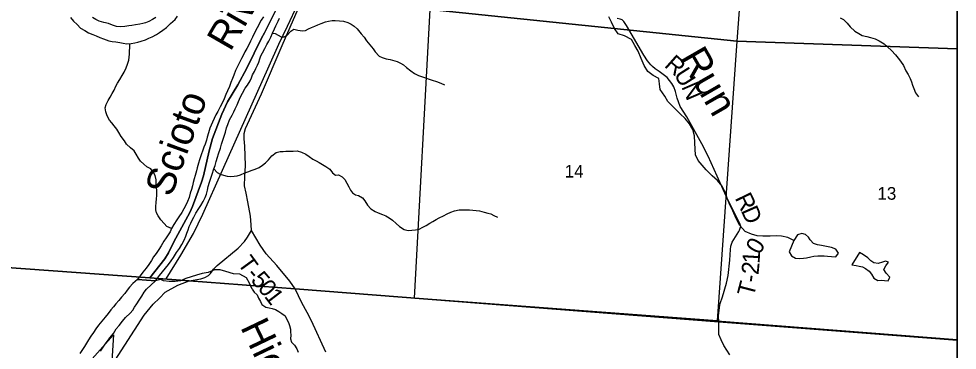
# Model space of a CAD drawing. Extents: x 5.6 to 39.6, y 0.7 to 22.7.
# Drawn here: x 11.957 to 15.052, y 17.991 to 19.086 of the extents above; entities that cross this region are included whole.
import ezdxf

# ---------------------------------------------------------------- set-up
doc = ezdxf.new("R2010")
doc.units = 0
doc.layers.add('Default', color=7, linetype='Continuous')
doc.layers.add('SH_Data', color=7, linetype='Continuous')

msp = doc.modelspace()

# ---------------------------------------------------------------- linework, layer by layer
at = {"layer": 'Default'}
for p, q in [((15.0518, 18.9873), (15.0518, 19.9373)), ((15.0518, 18.027), (15.0518, 18.9873)), ((12.4074, 18.221), (12.3477, 18.2256)), ((12.3477, 18.2256), (12.4074, 18.221))]:
    msp.add_line(p, q, dxfattribs=at)
for points in [[(15.0518, 18.0251), (15.0518, 21.7074), (8.2518, 21.7074), (8.2518, 18.5322)], [(15.0518, 18.0251), (15.0518, 21.7074), (8.2518, 21.7074), (8.2518, 18.5322)], [(15.0518, 18.0251), (15.0518, 21.7074), (10.4881, 21.7074)], [(15.0518, 19.9373), (14.3975, 19.9797), (14.3249, 19.0118), (15.0518, 18.9873)], [(10.5195, 18.3665), (12.3885, 18.2305), (12.4384, 18.2931), (12.4507, 18.3136), (12.4676, 18.3499), (12.5207, 18.446), (12.5299, 18.4665), (12.5594, 18.5468), (12.5656, 18.5673), (12.5844, 18.65), (12.5953, 18.691), (12.6263, 18.7713), (12.6456, 18.8122), (12.6786, 18.8682), (12.7086, 18.9228), (12.7572, 19.0227), (12.7672, 19.0401), (12.8142, 19.1341)], [(12.8142, 19.1341), (12.7672, 19.0401), (12.7572, 19.0227), (12.7086, 18.9228), (12.6786, 18.8682), (12.6456, 18.8122), (12.6263, 18.7713), (12.5953, 18.691), (12.5844, 18.65), (12.5656, 18.5673), (12.5594, 18.5468), (12.5299, 18.4665), (12.5207, 18.446), (12.4676, 18.3499), (12.4507, 18.3136), (12.4384, 18.2931), (12.3885, 18.2305), (12.519, 18.2209), (12.8677, 18.1945), (14.2655, 18.0848), (15.0518, 18.0251)], [(12.4428, 18.2276), (12.4916, 18.306), (12.5333, 18.3772), (12.5635, 18.4407), (12.6282, 18.5865), (12.7827, 18.9308), (12.8148, 19.0023), (12.8424, 19.0618), (12.8771, 19.1341)], [(12.519, 18.2209), (12.5566, 18.2268), (12.5707, 18.2322), (12.582, 18.2382), (12.5885, 18.2451), (12.5949, 18.2531), (12.5987, 18.2588), (12.6112, 18.2713), (12.6805, 18.3283), (12.701, 18.3507), (12.7112, 18.3648), (12.7244, 18.3867), (12.7236, 18.4055), (12.7205, 18.4347), (12.712, 18.4813), (12.7063, 18.5105), (12.7009, 18.5342), (12.7018, 18.565), (12.704, 18.602), (12.7021, 18.6657), (12.7002, 18.6892), (12.6999, 18.7076), (12.7041, 18.7233), (12.7567, 18.8386), (12.8253, 18.9985), (12.8776, 19.1189)], [(12.1272, 19.0901), (12.1377, 19.0786), (12.1492, 19.0671), (12.1604, 19.0555), (12.174, 19.0474), (12.1871, 19.04), (12.2011, 19.0338), (12.2116, 19.0295), (12.2244, 19.0244), (12.2361, 19.0197), (12.2538, 19.0134), (12.2652, 19.0114), (12.2773, 19.0097), (12.2901, 19.0077), (12.3011, 19.0053), (12.3135, 19.0036), (12.3272, 19.0042), (12.339, 19.0067), (12.3492, 19.0093), (12.3606, 19.0118), (12.3743, 19.0169), (12.3858, 19.0217), (12.3968, 19.0265), (12.4113, 19.0343), (12.4213, 19.0407), (12.432, 19.0485), (12.4435, 19.0575), (12.4573, 19.0706), (12.4722, 19.0834), (12.4807, 19.095)], [(12.4087, 19.0906), (12.3976, 19.0835), (12.3858, 19.0775), (12.3751, 19.0731), (12.3656, 19.0706), (12.3554, 19.0684), (12.3417, 19.0663), (12.3295, 19.0645), (12.3193, 19.0631), (12.306, 19.0606), (12.292, 19.0593), (12.2787, 19.0602), (12.2663, 19.0653), (12.2523, 19.0704), (12.2368, 19.074), (12.2214, 19.078), (12.2112, 19.0834), (12.2003, 19.0908)], [(12.4074, 18.221), (12.4211, 18.238), (12.4308, 18.2508), (12.4408, 18.2621), (12.4508, 18.2745), (12.4593, 18.2873), (12.4666, 18.2978), (12.4774, 18.3144), (12.4863, 18.3272), (12.4948, 18.3411), (12.5022, 18.3555), (12.5081, 18.3687), (12.5112, 18.3785), (12.5148, 18.3891), (12.5187, 18.4), (12.5238, 18.4117), (12.5285, 18.4215), (12.5339, 18.4313), (12.5405, 18.4442), (12.5506, 18.4592), (12.5568, 18.4694), (12.5649, 18.4826), (12.5715, 18.4958), (12.5762, 18.5075), (12.5794, 18.5204), (12.5815, 18.5321), (12.5858, 18.5468), (12.5945, 18.5733), (12.6004, 18.5907), (12.6047, 18.6017), (12.608, 18.6153), (12.6116, 18.6289), (12.6151, 18.6406), (12.6218, 18.6591), (12.6254, 18.6716), (12.6297, 18.6856), (12.6356, 18.7019), (12.6384, 18.7121), (12.642, 18.7257), (12.646, 18.7366), (12.6522, 18.7521), (12.6604, 18.7676), (12.6662, 18.7789), (12.6705, 18.7891), (12.6768, 18.8023), (12.6811, 18.8125), (12.6877, 18.828), (12.694, 18.8404), (12.7036, 18.8567), (12.7114, 18.8672), (12.7195, 18.8811), (12.7238, 18.891), (12.7277, 18.9012), (12.7336, 18.9117), (12.7382, 18.9219), (12.7437, 18.9332), (12.748, 18.9434), (12.7519, 18.9536), (12.7555, 18.9635), (12.7605, 18.9733), (12.7679, 18.9876), (12.7749, 19.0016), (12.7815, 19.0125), (12.7878, 19.0257), (12.7936, 19.0385), (12.8003, 19.0525), (12.805, 19.0634), (12.812, 19.0778), (12.817, 19.0887)], [(12.7633, 19.0932), (12.7563, 19.0815), (12.7431, 19.0566), (12.7322, 19.0355), (12.7275, 19.0257), (12.7213, 19.0128), (12.7155, 19.0007), (12.7092, 18.9883), (12.7026, 18.977), (12.6968, 18.9653), (12.6913, 18.9555), (12.6847, 18.9415), (12.6777, 18.9287), (12.6719, 18.9155), (12.6656, 18.9004), (12.6613, 18.8887), (12.6558, 18.8758), (12.6514, 18.8626), (12.6452, 18.8486), (12.6401, 18.8358), (12.6346, 18.8222), (12.6284, 18.8097), (12.621, 18.7958), (12.6128, 18.7803), (12.6062, 18.7686), (12.5957, 18.7448), (12.5914, 18.7346), (12.5871, 18.7248), (12.5823, 18.7093), (12.578, 18.6953), (12.5759, 18.6851), (12.5712, 18.6722), (12.5669, 18.6621), (12.5637, 18.6518), (12.5578, 18.6364)], [(12.7936, 19.0385), (12.8023, 19.0373), (12.8125, 19.0319), (12.8222, 19.0264), (12.8321, 19.0267), (12.8416, 19.0319), (12.8539, 19.045), (12.8639, 19.0521), (12.8775, 19.0485), (12.8922, 19.0461), (12.9028, 19.0478), (12.9124, 19.0527), (12.9219, 19.0571), (12.9333, 19.0623), (12.9433, 19.0667), (12.9535, 19.0708), (12.968, 19.0759), (12.9786, 19.0784), (12.9904, 19.0802), (12.9999, 19.0808), (13.0146, 19.0799), (13.0275, 19.0779), (13.0422, 19.0739), (13.0528, 19.0688), (13.0633, 19.0622), (13.073, 19.053), (13.086, 19.0369), (13.0957, 19.0258), (13.1039, 19.0139), (13.1147, 19.0005), (13.1255, 18.9871), (13.1326, 18.9768), (13.1453, 18.963), (13.1551, 18.9583), (13.1683, 18.954), (13.1815, 18.9515), (13.2041, 18.9456), (13.2154, 18.9401), (13.2259, 18.9339), (13.2357, 18.9255), (13.2495, 18.9139), (13.2623, 18.905), (13.2751, 18.8988), (13.2853, 18.8953), (13.2981, 18.891), (13.3102, 18.887), (13.3204, 18.8835), (13.3343, 18.8788), (13.3483, 18.8733), (13.3607, 18.8682)], [(14.5132, 18.3534), (14.4928, 18.3642), (14.4723, 18.3681), (14.4541, 18.369), (14.4351, 18.3677), (14.4108, 18.3679), (14.3919, 18.3695), (14.3737, 18.375), (14.3525, 18.3835), (14.3345, 18.4034), (14.3232, 18.427), (14.312, 18.4514), (14.3023, 18.4713), (14.2926, 18.4941), (14.2866, 18.5124), (14.2762, 18.5338), (14.2611, 18.5521), (14.2438, 18.5674), (14.2234, 18.5873), (14.1971, 18.6187), (14.1889, 18.637), (14.1875, 18.6552), (14.1869, 18.6765), (14.1855, 18.7001), (14.1796, 18.7206), (14.1683, 18.739), (14.1548, 18.7566), (14.1375, 18.7726), (14.1179, 18.7918), (14.0976, 18.8132), (14.0871, 18.8308), (14.072, 18.8522), (14.0699, 18.8712), (14.0677, 18.8887), (14.0488, 18.8987), (14.0315, 18.9118), (14.0195, 18.9324), (14.0098, 18.9552), (13.9993, 18.9789), (13.9881, 18.998), (13.9776, 19.0178), (13.9542, 19.0294), (13.933, 19.0364), (13.9218, 19.054), (13.912, 19.0746), (13.9023, 19.0929)], [(14.2655, 18.0848), (14.2646, 18.1053), (14.2678, 18.1329), (14.2699, 18.1454), (14.2771, 18.1676), (14.2907, 18.2125), (14.2965, 18.2382), (14.3016, 18.2886), (14.3037, 18.3238), (14.305, 18.3352), (14.3094, 18.3488), (14.3313, 18.3833), (14.334, 18.3882), (14.3364, 18.3946), (14.3384, 18.4006), (14.3344, 18.4098), (14.2894, 18.5004), (14.2301, 18.6323), (14.21, 18.6736), (14.1598, 18.7621), (14.1384, 18.7962), (14.1323, 18.8123), (14.1283, 18.8241), (14.123, 18.8458), (14.1176, 18.8615), (14.1107, 18.8726), (14.0947, 18.8922), (14.0824, 18.9023), (14.069, 18.912), (14.0555, 18.9206), (14.0473, 18.9283), (14.041, 18.9345), (14.0299, 18.9476), (14.0177, 18.9656), (13.9605, 19.0637), (13.9524, 19.0768), (13.9468, 19.0822), (13.94, 19.0853), (13.9299, 19.0874)], [(14.6657, 19.0896), (14.6762, 19.0841), (14.6886, 19.0715), (14.6983, 19.0592), (14.7136, 19.0458), (14.7275, 19.0373), (14.7384, 19.0314), (14.7535, 19.0275), (14.766, 19.0243), (14.7807, 19.0199), (14.7947, 19.0137), (14.8104, 19.0037), (14.8217, 18.994), (14.8348, 18.981), (14.8478, 18.9668), (14.8568, 18.9565), (14.8646, 18.9457), (14.8743, 18.932), (14.8828, 18.9144), (14.8898, 18.9018), (14.8961, 18.8885), (14.9005, 18.8778), (14.9046, 18.8675), (14.9086, 18.8557), (14.9141, 18.8416), (14.9241, 18.8286)], [(15.0518, 18.9873), (14.3249, 19.0118), (14.2605, 18.0881), (15.0518, 18.027)], [(12.4607, 18.3935), (12.4445, 18.4001), (12.4363, 18.4105), (12.4254, 18.4227), (12.4165, 18.4354), (12.4113, 18.4457), (12.4088, 18.4556), (12.4082, 18.4662), (12.4099, 18.4795), (12.4108, 18.4916), (12.4117, 18.503), (12.4115, 18.5193), (12.4105, 18.5295), (12.4096, 18.5447), (12.4094, 18.5542), (12.4065, 18.5687), (12.4013, 18.5786), (12.3924, 18.5905), (12.3789, 18.5971), (12.3691, 18.6056), (12.3583, 18.6163), (12.352, 18.6262), (12.3442, 18.6389), (12.3371, 18.6496), (12.3248, 18.6596), (12.3117, 18.6726), (12.305, 18.6826), (12.2946, 18.6979), (12.2868, 18.7109), (12.2797, 18.722), (12.2716, 18.7323), (12.2641, 18.7423), (12.2563, 18.7519), (12.2485, 18.7652), (12.2434, 18.7793), (12.2417, 18.7926), (12.2445, 18.8032), (12.2515, 18.8168), (12.2585, 18.8277), (12.265, 18.8391), (12.2709, 18.8508), (12.2771, 18.8636), (12.2826, 18.8738), (12.2896, 18.8855), (12.2977, 18.8986), (12.3043, 18.91), (12.3113, 18.9243), (12.3153, 18.936), (12.3192, 18.9493), (12.3209, 18.9595), (12.3214, 18.969), (12.3219, 18.9788), (12.3225, 18.9914), (12.3226, 19.0035)], [(12.5578, 18.6364), (12.5531, 18.6209), (12.5491, 18.6088), (12.5452, 18.5944), (12.5424, 18.5842), (12.538, 18.569), (12.5356, 18.5581), (12.532, 18.5452), (12.53, 18.5342), (12.526, 18.5225), (12.5224, 18.51), (12.5181, 18.4964), (12.513, 18.4832), (12.5071, 18.4704), (12.5009, 18.4587), (12.4943, 18.4466), (12.485, 18.4323), (12.4785, 18.4221), (12.4684, 18.4067), (12.4607, 18.3935), (12.456, 18.3829), (12.4494, 18.3731), (12.4432, 18.363), (12.4355, 18.3513), (12.4262, 18.3366), (12.4185, 18.3246), (12.4099, 18.3106), (12.4015, 18.2997), (12.3941, 18.2884), (12.3856, 18.2752), (12.3767, 18.2628), (12.3659, 18.2489), (12.3477, 18.2256)], [(12.6004, 18.5907), (12.6105, 18.5781), (12.6207, 18.573), (12.632, 18.5695), (12.6444, 18.5667), (12.6566, 18.5658), (12.6668, 18.566), (12.6774, 18.5674), (12.6877, 18.5711), (12.7022, 18.577), (12.7121, 18.5807), (12.7265, 18.5862), (12.7364, 18.5895), (12.7498, 18.5954), (12.7605, 18.6029), (12.7708, 18.6103), (12.7804, 18.6201), (12.7912, 18.634), (12.8057, 18.6444), (12.8183, 18.6477), (12.8282, 18.6484), (12.8376, 18.649), (12.8482, 18.6493), (12.8619, 18.6495), (12.8752, 18.6497), (12.8895, 18.6461), (12.903, 18.6387), (12.9139, 18.6318), (12.9267, 18.6229), (12.9372, 18.6167), (12.9474, 18.6113), (12.9583, 18.6047), (12.9692, 18.5985), (12.9827, 18.5896), (12.9917, 18.5778), (13.0014, 18.5697), (13.0109, 18.5703), (13.0233, 18.5645), (13.0315, 18.5549), (13.0382, 18.5434), (13.0452, 18.5308), (13.0508, 18.5205), (13.0575, 18.511), (13.0672, 18.5052), (13.0771, 18.5024), (13.0898, 18.4946), (13.0977, 18.4847), (13.1073, 18.4705), (13.1178, 18.4583), (13.1317, 18.4494), (13.1415, 18.4451), (13.1566, 18.44), (13.1671, 18.4357), (13.1788, 18.4291), (13.1889, 18.4214), (13.2016, 18.4103), (13.2125, 18.4003), (13.2275, 18.3898), (13.2411, 18.387), (13.2525, 18.3877), (13.2646, 18.389), (13.2768, 18.3919), (13.2898, 18.3975), (13.3004, 18.403), (13.3127, 18.4108), (13.3222, 18.4168), (13.3329, 18.4235), (13.3436, 18.4283), (13.3573, 18.4357), (13.3695, 18.442), (13.3817, 18.448), (13.3939, 18.4524), (13.4087, 18.4549), (13.4193, 18.4551), (13.4318, 18.4553), (13.4428, 18.4552), (13.4545, 18.4543), (13.4651, 18.4534), (13.4761, 18.4518), (13.4912, 18.4478), (13.5037, 18.4443), (13.5138, 18.4415), (13.5236, 18.4368), (13.5353, 18.431)], [(8.2518, 18.5322), (8.2518, 14.9074), (15.0518, 14.9074), (15.0518, 18.0251)], [(15.0518, 18.0251), (14.2655, 18.0848), (12.8677, 18.1945), (12.519, 18.2209), (12.3885, 18.2305), (10.5195, 18.3665), (9.8937, 18.4248), (8.2518, 18.5322)], [(8.2518, 18.5322), (8.2518, 14.9074), (15.0518, 14.9074), (15.0518, 18.0251)], [(15.0518, 18.0251), (14.2655, 18.0848), (12.8677, 18.1945), (12.519, 18.2209), (12.3885, 18.2305), (10.5195, 18.3665), (9.8937, 18.4248), (8.2518, 18.5322)], [(8.2518, 18.5322), (9.8937, 18.4248), (10.5195, 18.3665), (12.3885, 18.2305), (12.519, 18.2209), (12.8677, 18.1945), (14.2655, 18.0848), (15.0518, 18.0251)], [(8.2518, 18.5322), (9.8937, 18.4248), (10.5195, 18.3665), (12.3885, 18.2305), (12.519, 18.2209), (12.8677, 18.1945), (14.2655, 18.0848), (15.0518, 18.0251)], [(8.2518, 18.5322), (8.2518, 14.9074), (15.0518, 14.9074), (15.0518, 18.0251)], [(15.0518, 18.0251), (14.2655, 18.0848), (12.8677, 18.1945), (12.519, 18.2209), (12.3885, 18.2305), (10.5195, 18.3665), (9.8937, 18.4248), (8.2518, 18.5322)], [(12.8677, 18.1945), (12.8506, 18.22), (12.8078, 18.2714), (12.7727, 18.3104), (12.7533, 18.3384), (12.7244, 18.3867)], [(14.4976, 18.3165), (14.5054, 18.3035), (14.5189, 18.2961), (14.5318, 18.2948), (14.5451, 18.2954), (14.5549, 18.2972), (14.5694, 18.3004), (14.5789, 18.3022), (14.5921, 18.3032), (14.6126, 18.303), (14.6239, 18.3021), (14.6372, 18.3008), (14.6512, 18.2998), (14.6601, 18.3126), (14.6511, 18.3249), (14.6372, 18.3311), (14.6262, 18.3335), (14.6153, 18.3355), (14.6039, 18.3376), (14.5911, 18.3396), (14.5779, 18.3443), (14.5667, 18.3558), (14.5618, 18.3654), (14.5514, 18.3742), (14.5389, 18.3774), (14.5248, 18.3726)], [(14.5248, 18.3726), (14.5132, 18.3534), (14.4976, 18.3165)], [(14.7047, 18.2738), (14.7186, 18.2714), (14.7285, 18.2697), (14.739, 18.2673), (14.7488, 18.2619), (14.7608, 18.2527), (14.769, 18.2427), (14.7768, 18.2297), (14.7896, 18.2216), (14.8018, 18.2234), (14.8123, 18.2213), (14.8241, 18.2204), (14.8295, 18.2333), (14.8176, 18.2456), (14.8094, 18.2585), (14.816, 18.2706), (14.8248, 18.2822), (14.815, 18.2862), (14.8051, 18.2821), (14.7911, 18.2785), (14.7771, 18.2805), (14.7673, 18.2867), (14.7565, 18.2963), (14.7429, 18.3063), (14.7294, 18.3148)], [(14.7294, 18.3148), (14.7047, 18.2738)], [(12.7267, 18.1935), (12.7178, 18.2129), (12.708, 18.2305), (12.6854, 18.2428), (12.6649, 18.2437), (12.6399, 18.2515), (12.621, 18.257), (12.602, 18.2571), (12.5814, 18.2481), (12.5617, 18.2445), (12.5427, 18.2393), (12.5252, 18.2334), (12.5077, 18.2282), (12.4902, 18.2207), (12.4727, 18.2186), (12.453, 18.2187), (12.434, 18.2211), (12.4248, 18.2253), (12.4074, 18.221)], [(12.3477, 18.2256), (12.3332, 18.2122), (12.3213, 18.2002), (12.3144, 18.1897), (12.3067, 18.1787), (12.296, 18.1663), (12.2864, 18.1554), (12.2772, 18.1453), (12.2691, 18.1343), (12.2603, 18.1246), (12.2511, 18.1133), (12.2411, 18.1009), (12.2307, 18.0877), (12.2196, 18.0738), (12.2111, 18.0625), (12.2027, 18.0504), (12.1946, 18.038), (12.1869, 18.0259), (12.1803, 18.015), (12.173, 18.0033), (12.1665, 17.9935), (12.1576, 17.9803)], [(12.2259, 17.9888), (12.2351, 18.0012), (12.242, 18.011), (12.249, 18.0215), (12.257, 18.0321), (12.2689, 18.0471), (12.2778, 18.0618), (12.2878, 18.0735), (12.2985, 18.087), (12.3089, 18.0994), (12.3242, 18.1141), (12.3326, 18.1239), (12.3388, 18.134), (12.3465, 18.145), (12.3534, 18.1574), (12.3623, 18.1698), (12.3704, 18.1834), (12.3781, 18.1932), (12.4074, 18.221)], [(12.2748, 17.9582), (12.3701, 18.1073), (12.4002, 18.1436), (12.4208, 18.164), (12.44, 18.1838), (12.4813, 18.2067), (12.519, 18.2209)], [(12.7267, 18.1935), (12.7333, 18.1838), (12.7425, 18.1741), (12.7468, 18.1638), (12.7534, 18.153), (12.7585, 18.1431), (12.7715, 18.1333), (12.7821, 18.1311), (12.7919, 18.1294), (12.8035, 18.1261), (12.8144, 18.1198), (12.8241, 18.1128), (12.8349, 18.1046), (12.8399, 18.095), (12.8465, 18.0834), (12.8493, 18.0731), (12.8528, 18.0613), (12.853, 18.0518), (12.8542, 18.0411), (12.8532, 18.029), (12.8556, 18.0183), (12.866, 18.0079), (12.8736, 17.9959), (12.8783, 17.9856)], [(12.9698, 17.9855), (12.9223, 18.0883), (12.9083, 18.1164), (12.8904, 18.1483), (12.8677, 18.1945)], [(14.302, 17.9761), (14.2824, 18.0075), (14.2735, 18.0256), (14.2657, 18.0437), (14.2654, 18.0622), (14.2655, 18.0848)]]:
    msp.add_lwpolyline(points, dxfattribs=at)
for points in [[(13.3714, 20.1056), (14.3975, 19.9797), (14.3249, 19.0118), (13.3131, 19.1164)], [(13.3131, 19.1164), (14.3249, 19.0118), (14.2605, 18.0881), (13.2617, 18.164)], [(11.8073, 17.5238), (12.2692, 18.0419), (12.2127, 17.1504), (11.5163, 17.1975)]]:
    msp.add_lwpolyline(points, close=True, dxfattribs=at)
at = {"layer": 'SH_Data'}
msp.add_line((15.0518, 21.7074), (15.0518, 14.7074), dxfattribs=at)

# ---------------------------------------------------------------- texts
at = {"layer": 'Default'}
for s, height, rotation, p in [('River', 0.09483, 59.9704, (12.6545, 18.9752)), ('Run', 0.09471, 299.9516, (14.1331, 18.9577)), ('R', 0.0568, 318.3522, (14.0832, 18.9298)), ('U', 0.0568, 302.3917, (14.1153, 18.902)), ('N', 0.0568, 293.3655, (14.141, 18.8619)), ('Scioto', 0.09482, 69.9594, (12.4593, 18.494)), ('14', 0.04182, 0, (13.7573, 18.562)), ('R', 0.0568, 295.8817, (14.3172, 18.4944)), ('13', 0.04182, 0, (14.7886, 18.4886)), ('D', 0.0568, 293.8427, (14.3374, 18.4529)), ('0', 0.0568, 59.6677, (14.3997, 18.3046)), ('T', 0.0568, 305.9335, (12.676, 18.2781)), ('1', 0.0568, 86.7335, (14.3997, 18.2764)), ('2', 0.0568, 84.4413, (14.3961, 18.2391)), ('-', 0.0568, 310.1618, (12.7038, 18.2401)), ('5', 0.0568, 310.8097, (12.7193, 18.2217)), ('-', 0.0568, 81.0893, (14.392, 18.2124)), ('0', 0.0568, 310.4545, (12.7421, 18.1953)), ('T', 0.0568, 75.338, (14.38, 18.1652)), ('1', 0.0568, 307.4944, (12.7643, 18.1692)), ('Hickson', 0.09471, 295.6089, (12.686, 18.0681))]:
    msp.add_text(s, height=height, rotation=rotation, dxfattribs=at).set_placement(p)

doc.saveas('drawing.dxf')
